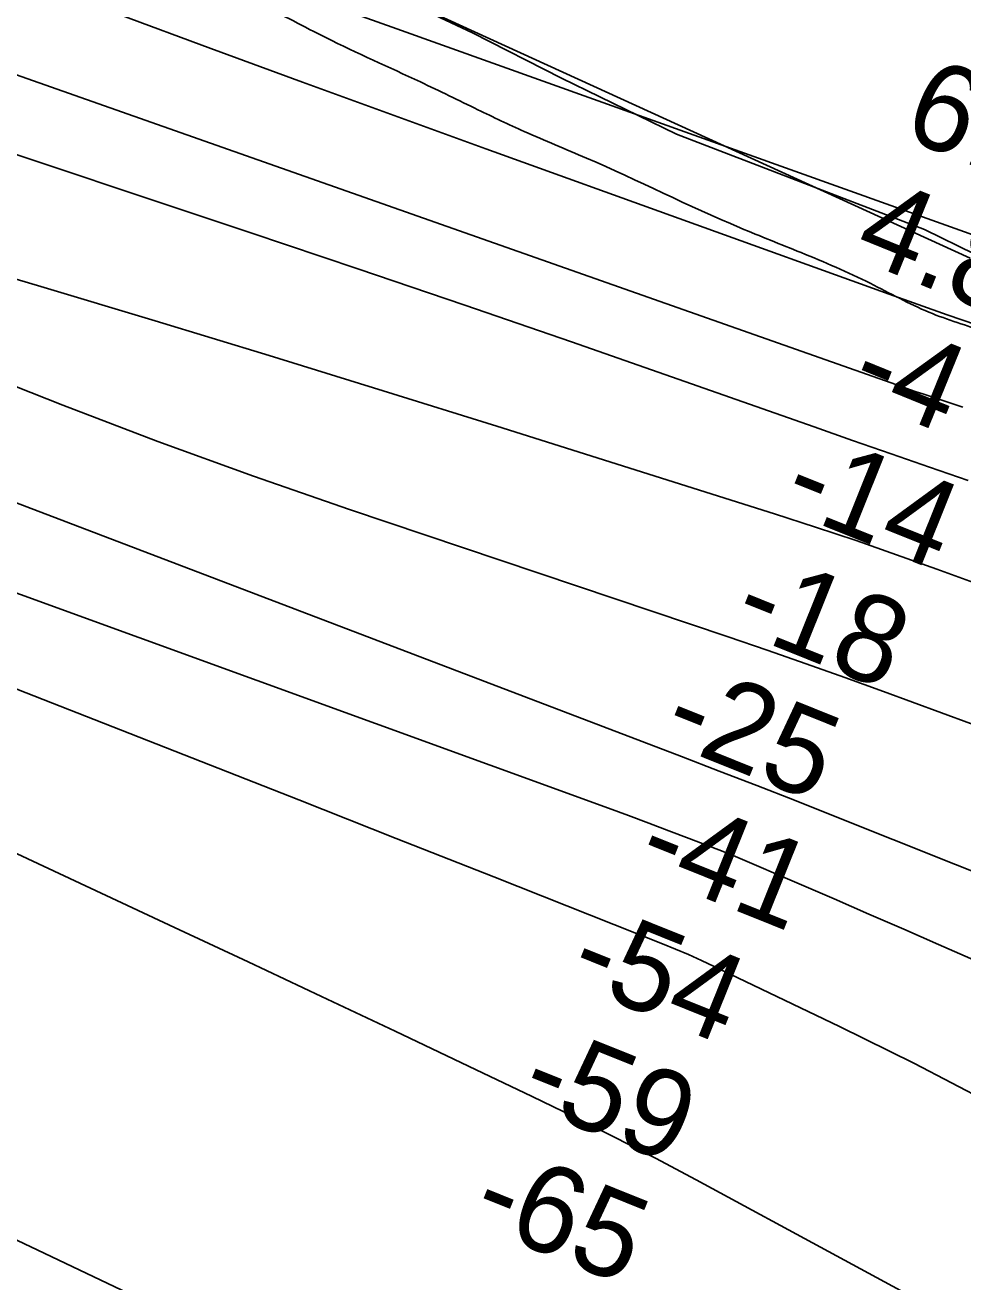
# Model space of a CAD drawing. Extents: x 3734862 to 3772949, y 391520 to 417239.
# Drawn here: x 3742082 to 3742804, y 406999 to 407967 of the extents above; entities that cross this region are included whole.
import ezdxf

# ---------------------------------------------------------------- set-up
doc = ezdxf.new("R2010")
doc.units = 0
for name, color, linetype in [('V-RIVR-EDGE', 7, 'Continuous'), ('V-RIVR-RANG', 7, 'Continuous'), ('V-RRAP-FSHR', 7, 'Continuous'), ('V-SITE-VEGE', 7, 'Continuous'), ('V-TOPO-DPTH', 7, 'Continuous'), ('V-TOPO-MAJR', 7, 'Continuous'), ('V-TOPO-MINR', 7, 'Continuous'), ('V-TOPO-WATR', 7, 'Continuous')]:
    doc.layers.add(name, color=color, linetype=linetype)

msp = doc.modelspace()

# ---------------------------------------------------------------- linework, layer by layer
at = {"layer": 'V-RIVR-EDGE'}
msp.add_spline([(3740900.5804832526, 408488.7607591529), (3740941.700981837, 408478.2594238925), (3740985.5366537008, 408468.65569270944), (3741012.202688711, 408464.06816566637), (3741026.2005238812, 408456.3468507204), (3741048.315927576, 408440.0144431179), (3741059.5974714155, 408430.9433678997), (3741079.4632746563, 408419.1381125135), (3741115.5910482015, 408400.96242050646), (3741134.5491848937, 408387.8029326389), (3741159.8363902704, 408374.1756358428), (3741187.834296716, 408359.637318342), (3741219.450570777, 408345.5422126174), (3741247.458539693, 408335.07330087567), (3741273.6657101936, 408327.7739547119), (3741324.259127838, 408308.2060164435), (3741367.6303449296, 408293.62968516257), (3741397.445820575, 408282.704145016), (3741437.1953158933, 408266.32813337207), (3741481.0086267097, 408247.6812782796), (3741515.791112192, 408234.0305023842), (3741546.0553898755, 408221.74737559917), (3741577.679490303, 408210.8173632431), (3741596.214540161, 408209.4150545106), (3741611.5923230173, 408211.18566551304), (3741627.866591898, 408209.7889470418), (3741654.51921028, 408199.77554565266), (3741683.8858838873, 408190.20759214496), (3741714.59896361, 408176.56687872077), (3741739.890641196, 408164.7482067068), (3741769.245016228, 408150.2065350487), (3741796.809773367, 408143.3559909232), (3741811.2776535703, 408142.86805705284), (3741832.9789148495, 408141.91007814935), (3741851.9627667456, 408139.1501827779), (3741871.853167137, 408137.29236369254), (3741889.019449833, 408130.9196909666), (3741941.855759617, 408104.11166330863), (3741978.426744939, 408082.31760368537), (3742006.4302416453, 408070.04006716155), (3742031.2820616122, 408063.1962313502), (3742056.132763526, 408055.90023934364), (3742093.6326583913, 408044.05137991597), (3742137.0083476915, 408031.2836734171), (3742175.8635930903, 408018.9793036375), (3742202.51509342, 408008.5137460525), (3742263.040294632, 407982.591023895), (3742313.1670213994, 407957.1461731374), (3742385.8803149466, 407923.0544520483), (3742430.1390736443, 407901.69354173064), (3742465.818045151, 407884.87543636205), (3742513.6962895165, 407864.40989401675), (3742632.029282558, 407810.7625332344), (3742679.00656869, 407791.6556955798), (3742732.3028610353, 407768.01164323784), (3742777.463696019, 407745.7441844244), (3742821.2848332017, 407730.2624227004), (3742862.3919151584, 407714.3352130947), (3742898.537577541, 407703.39402021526), (3742934.681003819, 407691.54851494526), (3742978.0555750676, 407678.32865225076), (3743028.200190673, 407660.11830062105), (3743075.641931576, 407645.98406306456), (3743127.6052344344, 407631.8386449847), (3743163.743070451, 407617.732358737), (3743235.1267286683, 407594.4957404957), (3743327.2916830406, 407563.97319271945), (3743354.8609123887, 407558.931273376), (3743372.940451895, 407556.1736141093), (3743388.7569743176, 407552.51723271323), (3743422.1841092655, 407539.32196717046), (3743470.5256903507, 407523.37686872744), (3743543.2837059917, 407507.37139545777), (3743582.5978159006, 407497.7788447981), (3743628.681970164, 407483.1958052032), (3743672.9563815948, 407468.16508162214), (3743714.522328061, 407454.9496911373), (3743752.478851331, 407444.9083384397), (3743782.3122158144, 407441.2172974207), (3743812.5921462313, 407435.2643573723), (3743846.038288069, 407429.75574715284), (3743877.2147045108, 407420.63547763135), (3743909.2808986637, 407405.63494146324), (3743934.1014131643, 407386.1307321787), (3743951.2453348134, 407370.7149355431), (3743984.2001886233, 407349.3819765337), (3744023.0464896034, 407333.4603571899), (3744065.9756129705, 407322.95454972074), (3744101.675827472, 407314.7274120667), (3744133.7587924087, 407306.50921883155), (3744170.3599651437, 407296.92337648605), (3744207.4121760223, 407286.884259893), (3744225.0339690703, 407281.86693770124), (3744312.23862192, 407256.7825628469), (3744386.801908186, 407239.4161487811), (3744416.179762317, 407234.36975722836), (3744442.3969952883, 407231.13981682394), (3744469.5274850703, 407231.5248898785), (3744498.9198738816, 407232.35652886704), (3744525.594853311, 407231.3862513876), (3744550.005697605, 407229.06509558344), (3744580.7321939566, 407220.850256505), (3744636.7637845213, 407206.2426197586), (3744682.3857201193, 407187.5912924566), (3744706.329873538, 407179.39322416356), (3744748.361392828, 407171.602589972), (3744781.8041805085, 407164.7375111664), (3744803.051049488, 407162.87633792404), (3744835.5772262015, 407151.03977707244), (3744852.283526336, 407141.50312903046), (3744920.944184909, 407114.20381334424), (3744972.8773003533, 407087.85017798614), (3745004.947966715, 407074.6582666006), (3745034.319112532, 407066.8989378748), (3745066.8575878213, 407060.0360951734), (3745090.817393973, 407058.1682136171), (3745113.40731491, 407050.8778118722), (3745145.9211930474, 407034.06753287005), (3745173.0181412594, 407020.8879200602), (3745183.3730116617, 407002.775957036), (3745197.806232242, 406988.2711811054), (3745221.284812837, 406974.64835651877), (3745251.1047606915, 406965.53144115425), (3745295.845862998, 406956.3776300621), (3745336.0832921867, 406954.46949862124), (3745373.6077842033, 406952.568075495), (3745407.9593564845, 406947.5093853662), (3745449.9897577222, 406939.26659497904), (3745482.9826253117, 406933.30694661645), (3745526.394092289, 406935.00823837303), (3745594.221993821, 406936.64915530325), (3745631.750958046, 406936.55635695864), (3745647.5876054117, 406941.03878708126), (3745660.719141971, 406948.6930188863), (3745673.8327896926, 406949.1127515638), (3745691.0091348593, 406946.80948459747), (3745714.498895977, 406937.7082219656), (3745744.7553472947, 406922.2600018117), (3745760.5428003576, 406906.8475593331), (3745773.1618058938, 406890.08647463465), (3745781.290554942, 406885.9969439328), (3745798.0080355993, 406880.98185784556), (3745819.7081788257, 406879.5717227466), (3745874.386654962, 406866.32390874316), (3745905.104206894, 406854.4918201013), (3745930.8379782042, 406838.6026242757), (3745969.2108799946, 406814.09115526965), (3745999.0162931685, 406799.0962093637), (3746028.82953271, 406787.2663568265), (3746069.4978750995, 406776.7661396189), (3746110.167335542, 406766.71807860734), (3746144.959883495, 406757.1367084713), (3746173.873282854, 406747.1177168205), (3746214.5427432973, 406737.0696558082), (3746271.4786462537, 406722.4597829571), (3746336.102322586, 406708.2830594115), (3746374.5031756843, 406695.07549529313), (3746423.295794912, 406678.67712260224), (3746514.1210514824, 406654.940271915), (3746563.3725352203, 406641.25371834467), (3746619.392945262, 406622.1245196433), (3746668.6388387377, 406606.1771850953), (3746708.3995145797, 406594.3227354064), (3746774.3651248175, 406574.26462716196), (3746826.3396081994, 406564.6407710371), (3746866.124881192, 406562.73375764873), (3746897.312478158, 406558.135050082), (3746931.657342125, 406550.36342278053)], degree=3, dxfattribs=at)
at = {"layer": 'V-RRAP-FSHR'}
for points in [[(3738902.293381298, 409472.05737969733), (3740332.6069263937, 408753.8471600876), (3741222.946255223, 408371.2807597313), (3742367.6717602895, 407964.03391135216)], [(3742367.6717602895, 407964.03391135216), (3744035.923409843, 407366.7900067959), (3745769.795027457, 406946.2127264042), (3746228.760019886, 406810.1436062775), (3747274.1821008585, 406525.63749401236), (3748829.568470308, 406241.1293337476), (3749734.751703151, 405944.253301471), (3750537.9424878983, 405672.1150612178), (3750818.4201841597, 405622.6374291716)]]:
    msp.add_lwpolyline(points, dxfattribs=at)
at = {"layer": 'V-SITE-VEGE'}
msp.add_lwpolyline([(3742851.665, 407771.442), (3742774.046, 407809.471), (3742583.023, 407882.913), (3742494.488, 407925.853), (3742426.056, 407960.89), (3742396.946, 407974.391)], dxfattribs=at)
at = {"layer": 'V-TOPO-DPTH'}
for points in [[(3741344.1757719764, 408256.8803595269), (3741361.763542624, 408250.8929114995), (3741379.3922432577, 408245.0237309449), (3741519.8005438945, 408199.0638355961), (3741602.4312121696, 408171.63878150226), (3741684.9068352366, 408143.76118395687), (3741767.1498904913, 408115.2047712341), (3741849.2379005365, 408086.19581505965), (3741944.277962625, 408052.16852125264), (3741978.705863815, 408039.76864273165), (3742013.1020652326, 408027.2819560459), (3742047.450716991, 408014.6650571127), (3742081.7676689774, 408001.96135001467), (3742154.060026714, 407975.0438151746), (3742224.5397753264, 407948.9264685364), (3742295.073380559, 407922.9561001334), (3742365.6877707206, 407897.20619908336), (3742436.3560175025, 407871.60327626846), (3742746.9182101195, 407759.6358470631), (3742769.2256532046, 407751.6652469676), (3742791.5628874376, 407743.77981111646), (3742813.9448083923, 407736.02212163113)], [(3742807.6368422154, 407616.30608748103), (3742777.9447145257, 407626.4862109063), (3742748.2722379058, 407636.7230311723), (3742718.629237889, 407647.0448966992), (3742689.005888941, 407657.4234590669), (3742584.292799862, 407694.278416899), (3742502.2553190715, 407722.91572695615), (3742420.121409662, 407751.27138134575), (3742337.8428573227, 407779.2045522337), (3742255.467876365, 407806.8560674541), (3742015.1876293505, 407886.8265702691), (3741986.610928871, 407896.57519909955), (3741958.136234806, 407906.6066211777), (3741929.814550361, 407917.06223312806), (3741901.594872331, 407927.8006383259), (3741856.928760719, 407945.18040704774), (3741806.66022129, 407965.3071471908), (3741756.6683046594, 407986.08164415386), (3741707.091322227, 408007.82777634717), (3741657.7909625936, 408030.22166536), (3741263.8529723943, 408213.82029983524)], [(3742807.6368422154, 407616.30608748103), (3742777.9447145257, 407626.4862109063), (3742748.2722379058, 407636.7230311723), (3742718.629237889, 407647.0448966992), (3742689.005888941, 407657.4234590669), (3742584.292799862, 407694.278416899), (3742502.2553190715, 407722.91572695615), (3742420.121409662, 407751.27138134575), (3742337.8428573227, 407779.2045522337), (3742255.467876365, 407806.8560674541), (3742015.1876293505, 407886.8265702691), (3741986.610928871, 407896.57519909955), (3741958.136234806, 407906.6066211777), (3741929.814550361, 407917.06223312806), (3741901.594872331, 407927.8006383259), (3741856.928760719, 407945.18040704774), (3741806.66022129, 407965.3071471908), (3741756.6683046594, 407986.08164415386), (3741707.091322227, 408007.82777634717), (3741657.7909625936, 408030.22166536), (3741263.8529723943, 408213.82029983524)], [(3741303.2086549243, 408038.59236719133), (3741875.704717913, 407769.8485268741), (3741884.1004568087, 407765.9881997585), (3741892.535302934, 407762.2172399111), (3741901.028809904, 407758.5803309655), (3741909.5614241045, 407755.03278928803), (3742037.627251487, 407702.97343378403), (3742110.472635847, 407674.138011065), (3742183.651771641, 407646.20152959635), (3742257.3315345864, 407619.61346000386), (3742331.345048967, 407593.9243316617), (3742622.964575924, 407495.6979496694), (3742652.970221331, 407485.45637648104), (3742682.9193564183, 407475.0541934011), (3742712.783726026, 407464.4110954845), (3742742.5915853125, 407453.6073876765), (3742831.699809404, 407420.9039037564)], [(3741303.2086549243, 408038.59236719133), (3741875.704717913, 407769.8485268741), (3741884.1004568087, 407765.9881997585), (3741892.535302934, 407762.2172399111), (3741901.028809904, 407758.5803309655), (3741909.5614241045, 407755.03278928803), (3742037.627251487, 407702.97343378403), (3742110.472635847, 407674.138011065), (3742183.651771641, 407646.20152959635), (3742257.3315345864, 407619.61346000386), (3742331.345048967, 407593.9243316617), (3742622.964575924, 407495.6979496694), (3742652.970221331, 407485.45637648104), (3742682.9193564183, 407475.0541934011), (3742712.783726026, 407464.4110954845), (3742742.5915853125, 407453.6073876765), (3742831.699809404, 407420.9039037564)], [(3742844.7981195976, 407301.90523554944), (3742702.7304001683, 407358.52773506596), (3742673.8711811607, 407369.95463258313), (3742644.978114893, 407381.2947174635), (3742616.034277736, 407392.5045833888), (3742587.0565933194, 407403.6276366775), (3741961.370696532, 407642.18160103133), (3741943.8551074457, 407648.8866333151), (3741926.351597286, 407655.62292630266), (3741908.8662055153, 407662.40611034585), (3741891.3928926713, 407669.2205550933), (3741861.4703462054, 407680.9363207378), (3741858.971695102, 407681.9269388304), (3741856.4788152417, 407682.9317015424), (3741853.9945922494, 407683.9576811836), (3741851.5161405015, 407684.99780544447), (3741378.9779687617, 407885.6799250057), (3741329.913633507, 407906.7632462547)], [(3742844.7981195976, 407301.90523554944), (3742702.7304001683, 407358.52773506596), (3742673.8711811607, 407369.95463258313), (3742644.978114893, 407381.2947174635), (3742616.034277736, 407392.5045833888), (3742587.0565933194, 407403.6276366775), (3741961.370696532, 407642.18160103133), (3741943.8551074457, 407648.8866333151), (3741926.351597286, 407655.62292630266), (3741908.8662055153, 407662.40611034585), (3741891.3928926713, 407669.2205550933), (3741861.4703462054, 407680.9363207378), (3741858.971695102, 407681.9269388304), (3741856.4788152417, 407682.9317015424), (3741853.9945922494, 407683.9576811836), (3741851.5161405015, 407684.99780544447), (3741378.9779687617, 407885.6799250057), (3741329.913633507, 407906.7632462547)], [(3741898.268976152, 407593.5900557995), (3742530.669735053, 407363.86651510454), (3742546.2347474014, 407358.1623465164), (3742561.7777746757, 407352.3993954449), (3742577.287824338, 407346.54827064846), (3742592.7758889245, 407340.638363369), (3742618.916731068, 407330.57846245), (3742621.3122762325, 407329.6406399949), (3742623.700345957, 407328.6844559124), (3742626.077202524, 407327.70072938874), (3742628.446583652, 407326.698641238), (3742677.5030477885, 407305.61595616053), (3742704.3835467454, 407294.03221851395), (3742731.2487046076, 407282.4131058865), (3742758.0908508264, 407270.7409307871), (3742784.9176559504, 407259.0333807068), (3743453.566915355, 406966.43978016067)], [(3741898.268976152, 407593.5900557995), (3742530.669735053, 407363.86651510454), (3742546.2347474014, 407358.1623465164), (3742561.7777746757, 407352.3993954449), (3742577.287824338, 407346.54827064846), (3742592.7758889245, 407340.638363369), (3742618.916731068, 407330.57846245), (3742621.3122762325, 407329.6406399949), (3742623.700345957, 407328.6844559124), (3742626.077202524, 407327.70072938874), (3742628.446583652, 407326.698641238), (3742677.5030477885, 407305.61595616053), (3742704.3835467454, 407294.03221851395), (3742731.2487046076, 407282.4131058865), (3742758.0908508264, 407270.7409307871), (3742784.9176559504, 407259.0333807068), (3743453.566915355, 406966.43978016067)]]:
    msp.add_lwpolyline(points, dxfattribs=at)
at = {"layer": 'V-TOPO-MAJR'}
msp.add_lwpolyline([(3742823.4137506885, 407137.5106654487), (3742766.3322627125, 407167.21673891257), (3742708.6739724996, 407195.8518213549), (3742612.192384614, 407242.0738426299), (3742602.295761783, 407246.6885403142), (3742592.3382417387, 407251.16386602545), (3742582.2893758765, 407255.4301337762), (3742572.179612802, 407259.5570295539), (3742442.3774965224, 407310.967488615), (3742367.3052700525, 407340.6551692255), (3742292.212128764, 407370.2897699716), (3742217.0876152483, 407399.84475092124), (3742141.9421869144, 407429.3466520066), (3741836.6467029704, 407549.01815257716), (3741819.2695868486, 407555.9705650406), (3741801.960042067, 407563.08417767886), (3741784.751854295, 407570.4395905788), (3741767.611237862, 407577.95620365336), (3741538.50413708, 407680.3453088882), (3741454.4156139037, 407718.4557964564), (3741370.601035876, 407757.1515525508), (3741287.197375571, 407796.7252114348)], dxfattribs=at)
at = {"layer": 'V-TOPO-MINR'}
for points in [[(3742803.59199821, 407672.5649234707), (3742778.1067845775, 407681.03993041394), (3742772.8652696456, 407682.7983173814), (3742767.6300411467, 407684.5750683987), (3742762.404242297, 407686.37936549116), (3742757.1847298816, 407688.2020266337), (3741982.88, 407960.88), (3741639.5684787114, 408090.9699588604), (3741567.4514388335, 408119.09262547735), (3741495.715283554, 408148.13083503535), (3741424.550455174, 408178.54235900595), (3741353.7665113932, 408209.86942591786), (3741248.695523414, 408257.58388049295), (3741230.7895914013, 408265.8586564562), (3741212.959108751, 408274.2902911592), (3741195.241800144, 408282.9572139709), (3741177.5999408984, 408291.78099552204), (3741042.605867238, 408360.4206770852), (3740957.5210023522, 408403.6769169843), (3740872.432699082, 408446.92639126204), (3740787.3392382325, 408490.16571710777), (3740702.2423389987, 408533.39827733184), (3740440.9891087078, 408666.1055584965)], [(3742809.25, 407787.49), (3742137.5557717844, 408094.25004957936), (3742098.4485726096, 408111.5792981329), (3742059.096240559, 408128.31352971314), (3742019.376209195, 408144.15523583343), (3741979.411044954, 408159.40192498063), (3741778.0340889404, 408233.63395142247), (3741719.0995901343, 408254.0894898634), (3741659.7123465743, 408273.02557149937), (3741599.645985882, 408289.6824679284), (3741539.126880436, 408304.8199075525), (3741453.958710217, 408324.40333261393), (3741435.7359336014, 408328.80284139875), (3741417.5836769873, 408333.4650213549), (3741399.5372003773, 408338.5212080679), (3741381.56124377, 408343.8400659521), (3741363.7013661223, 408349.5387312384), (3741345.925580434, 408355.48060808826)], [(3742807.6368422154, 407616.30608748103), (3742777.9447145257, 407626.4862109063), (3742748.2722379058, 407636.7230311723), (3742718.629237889, 407647.0448966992), (3742689.005888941, 407657.4234590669), (3742584.292799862, 407694.278416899), (3742502.2553190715, 407722.91572695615), (3742420.121409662, 407751.27138134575), (3742337.8428573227, 407779.2045522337), (3742255.467876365, 407806.8560674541), (3742015.1876293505, 407886.8265702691), (3741986.610928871, 407896.57519909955), (3741958.136234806, 407906.6066211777), (3741929.814550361, 407917.06223312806), (3741901.594872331, 407927.8006383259), (3741856.928760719, 407945.18040704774), (3741806.66022129, 407965.3071471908), (3741756.6683046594, 407986.08164415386), (3741707.091322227, 408007.82777634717), (3741657.7909625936, 408030.22166536), (3741263.8529723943, 408213.82029983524)], [(3742856.978258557, 407521.2356300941), (3742783.5537218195, 407547.97745225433), (3742752.471158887, 407559.06874864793), (3742721.2962235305, 407569.88816899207), (3742689.982729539, 407580.2997752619), (3742658.5768631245, 407590.4395054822), (3742444.8134701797, 407657.9180251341), (3742357.21352027, 407685.32660764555), (3742269.522675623, 407712.438537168), (3742181.6954888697, 407739.1054872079), (3742093.77740738, 407765.4757842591), (3741972.6460473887, 407801.473654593), (3741945.393630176, 407810.0882583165), (3741918.364805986, 407819.32213933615), (3741891.671371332, 407829.48493630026), (3741865.2015297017, 407840.267010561), (3741786.2605555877, 407874.02583203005), (3741720.8190694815, 407902.8550246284), (3741655.818014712, 407932.61914955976), (3741591.4776069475, 407963.7856729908), (3741527.57763052, 407995.88712875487), (3741205.002098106, 408162.3445433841)], [(3742831.699809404, 407420.9039037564), (3742742.5915853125, 407453.6073876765), (3742712.783726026, 407464.4110954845), (3742682.9193564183, 407475.0541934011), (3742652.970221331, 407485.45637648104), (3742622.964575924, 407495.6979496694), (3742331.345048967, 407593.9243316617), (3742257.3315345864, 407619.61346000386), (3742183.651771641, 407646.20152959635), (3742110.472635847, 407674.138011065), (3742037.627251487, 407702.97343378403), (3741909.5614241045, 407755.03278928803), (3741901.028809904, 407758.5803309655), (3741892.535302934, 407762.2172399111), (3741884.1004568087, 407765.9881997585), (3741875.704717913, 407769.8485268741), (3741303.2086549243, 408038.59236719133)], [(3742844.7981195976, 407301.90523554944), (3742702.7304001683, 407358.52773506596), (3742673.8711811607, 407369.95463258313), (3742644.978114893, 407381.2947174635), (3742616.034277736, 407392.5045833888), (3742587.0565933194, 407403.6276366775), (3741961.370696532, 407642.18160103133), (3741943.8551074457, 407648.8866333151), (3741926.351597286, 407655.62292630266), (3741908.8662055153, 407662.40611034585), (3741891.3928926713, 407669.2205550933), (3741861.4703462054, 407680.9363207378), (3741858.971695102, 407681.9269388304), (3741856.4788152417, 407682.9317015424), (3741853.9945922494, 407683.9576811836), (3741851.5161405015, 407684.99780544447), (3741378.9779687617, 407885.6799250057), (3741329.913633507, 407906.7632462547)], [(3742814.2216831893, 406960.6929424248), (3742598.1841793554, 407077.77998069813), (3742566.9053676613, 407094.41494996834), (3742535.4579641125, 407110.7183602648), (3742503.7576727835, 407126.524432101), (3742471.8887896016, 407141.99894496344), (3742422.8758531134, 407165.3228075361), (3742366.3472885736, 407192.15385389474), (3742309.783128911, 407218.90945333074), (3742253.165576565, 407245.5518823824), (3742196.5124290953, 407272.11886451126), (3741792.3184419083, 407461.1691875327), (3741777.251537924, 407468.37061804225), (3741762.268250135, 407475.73855492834), (3741747.4103866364, 407483.35625138), (3741732.636139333, 407491.14045420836), (3741393.4533649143, 407673.49120497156), (3741330.715421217, 407707.0144011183)], [(3742434.33, 406860.44), (3741651.7, 407232.65), (3740934.1294072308, 407640.9899911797)], [(3743453.566915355, 406966.43978016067), (3742784.9176559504, 407259.0333807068), (3742758.0908508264, 407270.7409307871), (3742731.2487046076, 407282.4131058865), (3742704.3835467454, 407294.03221851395), (3742677.5030477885, 407305.61595616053), (3742628.446583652, 407326.698641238), (3742626.077202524, 407327.70072938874), (3742623.700345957, 407328.6844559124), (3742621.3122762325, 407329.6406399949), (3742618.916731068, 407330.57846245), (3742592.7758889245, 407340.638363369), (3742577.287824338, 407346.54827064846), (3742561.7777746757, 407352.3993954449), (3742546.2347474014, 407358.1623465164), (3742530.669735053, 407363.86651510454), (3741898.268976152, 407593.5900557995)]]:
    msp.add_lwpolyline(points, dxfattribs=at)
at = {"layer": 'V-TOPO-WATR'}
msp.add_lwpolyline([(3742813.9448083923, 407736.02212163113), (3742791.5628874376, 407743.77981111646), (3742769.2256532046, 407751.6652469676), (3742746.9182101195, 407759.6358470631), (3742436.3560175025, 407871.60327626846), (3742365.6877707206, 407897.20619908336), (3742295.073380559, 407922.9561001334), (3742224.5397753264, 407948.9264685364), (3742154.060026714, 407975.0438151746), (3742081.7676689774, 408001.96135001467), (3742047.450716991, 408014.6650571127), (3742013.1020652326, 408027.2819560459), (3741978.705863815, 408039.76864273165), (3741944.277962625, 408052.16852125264), (3741849.2379005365, 408086.19581505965), (3741767.1498904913, 408115.2047712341), (3741684.9068352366, 408143.76118395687), (3741602.4312121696, 408171.63878150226), (3741519.8005438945, 408199.0638355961), (3741379.3922432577, 408245.0237309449), (3741361.763542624, 408250.8929114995), (3741344.1757719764, 408256.8803595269)], dxfattribs=at)

# ---------------------------------------------------------------- texts
at = {"layer": 'V-RIVR-RANG'}
for s, height, rotation, p in [('6.2', 67, 337.8383257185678, (3742754.9593725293, 407881.4089372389)), ('4.8', 67, 337.8383257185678, (3742717.466372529, 407788.70293723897)), ('-4', 67, 337.8383257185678, (3742713.685712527, 407682.26648502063)), ('-14', 66.99999999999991, 338.1217222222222, (3742662.0580103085, 407594.9754244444)), ('-18', 66.99999999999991, 338.1217222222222, (3742623.8306658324, 407502.5643056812)), ('-25', 66.99999999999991, 338.1217222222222, (3742569.692524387, 407416.54328037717)), ('-41', 66.99999999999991, 338.1217222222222, (3742549.5800103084, 407316.85942444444)), ('-54', 66.99999999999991, 338.1217222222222, (3742497.4001207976, 407230.0510491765)), ('-59', 66.99999999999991, 338.1217222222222, (3742459.9071207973, 407137.34604917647)), ('-65', 66.99999999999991, 338.1217222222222, (3742422.6589022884, 407044.542755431))]:
    msp.add_text(s, height=height, rotation=rotation, dxfattribs=at).set_placement(p)

doc.saveas('drawing.dxf')
